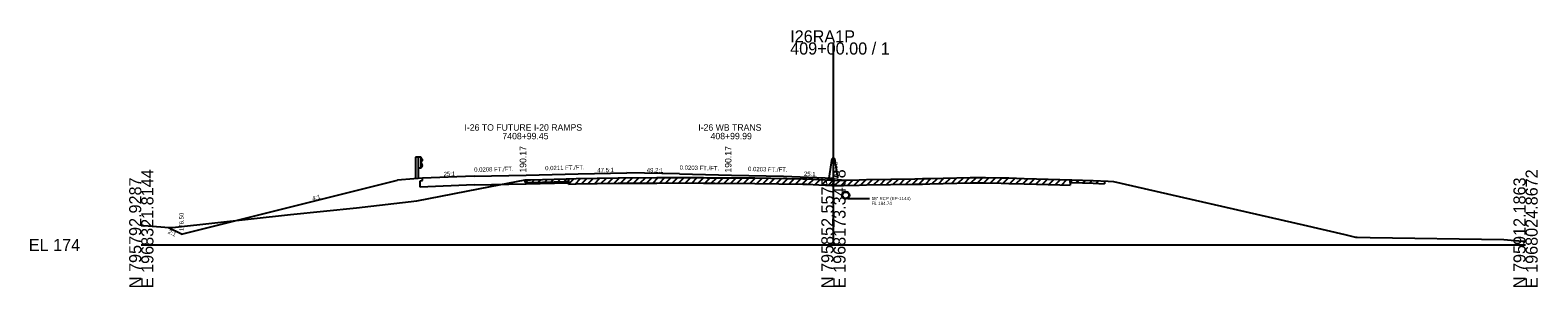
# Model space of a CAD drawing. Extents: x -44 to 4323, y -10 to 9601.
# Drawn here: x -25.7 to 322.8, y 5990.3 to 6049.7 of the extents above; entities that cross this region are included whole.
import ezdxf

# ---------------------------------------------------------------- set-up
doc = ezdxf.new("R2010")
doc.units = 0
for name, color, linetype in [('1', 7, 'Continuous'), ('DateStamp', 7, 'Continuous'), ('NotForConst', 7, 'Continuous'), ('QCQA', 7, 'Continuous'), ('RD_SHT_Bndy', 7, 'Continuous'), ('RD_SHT_Iplotshp', 7, 'Continuous'), ('RD_SHT_TX', 7, 'Continuous'), ('RD_XS_Base', 7, 'Continuous'), ('RD_XS_ExGround', 7, 'Continuous'), ('RD_XS_Misc_Line', 7, 'Continuous'), ('RD_XS_Pave', 7, 'Continuous'), ('RD_XS_PaveShd', 7, 'Continuous'), ('RD_XS_Pipe', 7, 'Continuous'), ('RD_XS_TX_Elev_PR', 7, 'Continuous'), ('RD_XS_TX_ShdSlope', 7, 'Continuous'), ('RD_XS_TX_Slope', 7, 'Continuous'), ('seal', 7, 'Continuous'), ('TR SN EXTRUDED PANEL SIGNS - GROUND MOUNTED', 7, 'Continuous')]:
    doc.layers.add(name, color=color, linetype=linetype)

msp = doc.modelspace()

# ---------------------------------------------------------------- linework, layer by layer
at = {"layer": 'DateStamp'}
msp.add_lwpolyline([(0, 6004.5), (0.57, 6004.47), (6.43, 6004), (7.94, 6004.11), (34.51, 6007.01), (49.78, 6008.61), (63.66, 6010.17), (80.69, 6013.52), (88.75, 6015.06), (89.96, 6015.09), (98.2, 6015.31), (100.53, 6015.35), (110.25, 6015.5), (119.14, 6015.56), (121.94, 6015.59), (129.97, 6015.56), (130.77, 6015.55), (132.56, 6015.54), (141.86, 6015.49), (152.91, 6015.31), (153.94, 6015.29), (156.59, 6015.15), (159.65, 6014.98), (160, 6014.98), (162.31, 6014.99), (165.96, 6015.08), (167.66, 6015.12), (178.84, 6015.3), (180.57, 6015.33), (182.29, 6015.36), (191.59, 6015.58), (192.15, 6015.58), (193.43, 6015.61), (195.13, 6015.6), (198.74, 6015.52), (200.51, 6015.49), (204.13, 6015.38), (206.92, 6015.3), (212.33, 6015.16), (215.08, 6015.07), (220.03, 6014.91), (223.53, 6014.76), (224.74, 6014.71), (268.61, 6004.62), (278.22, 6002.42), (280.71, 6001.82), (281.07, 6001.82), (284.08, 6001.72), (315.01, 6001.29), (319.29, 6000.87), (320, 6000.91)], dxfattribs=at)
at = {"layer": 'NotForConst'}
for p, q in [((88.75, 6014.43), (89.4, 6015.07)), ((90.25, 6014.47), (90.9, 6015.11)), ((91.76, 6014.51), (92.4, 6015.15)), ((93.26, 6014.55), (93.9, 6015.19)), ((94.76, 6014.59), (95.4, 6015.23)), ((96.26, 6014.63), (96.9, 6015.27)), ((97.76, 6014.67), (98.4, 6015.31)), ((98.76, 6014.07), (100.03, 6015.34)), ((100.26, 6014.09), (101.53, 6015.36)), ((101.76, 6014.12), (103.03, 6015.39)), ((103.26, 6014.14), (104.53, 6015.41)), ((104.76, 6014.16), (106.03, 6015.43)), ((106.26, 6014.19), (107.53, 6015.46)), ((107.76, 6014.21), (109.03, 6015.48)), ((109.26, 6014.24), (110.53, 6015.5)), ((110.76, 6014.26), (112.02, 6015.51)), ((112.26, 6014.27), (113.52, 6015.52)), ((113.76, 6014.28), (115.02, 6015.53)), ((115.26, 6014.29), (116.52, 6015.54)), ((116.76, 6014.3), (118.02, 6015.55)), ((118.26, 6014.31), (119.52, 6015.57)), ((119.76, 6014.32), (121.02, 6015.58)), ((121.26, 6014.33), (122.51, 6015.59)), ((122.76, 6014.34), (124.01, 6015.58)), ((124.26, 6014.33), (125.51, 6015.57)), ((125.76, 6014.32), (127.01, 6015.57)), ((127.26, 6014.32), (128.51, 6015.56)), ((128.76, 6014.31), (130.01, 6015.56)), ((130.26, 6014.31), (131.51, 6015.55)), ((131.76, 6014.3), (133.01, 6015.54)), ((133.26, 6014.29), (134.51, 6015.53)), ((134.76, 6014.28), (136.01, 6015.53)), ((136.26, 6014.27), (137.51, 6015.52)), ((137.76, 6014.27), (139.01, 6015.51)), ((139.26, 6014.26), (140.51, 6015.5)), ((140.76, 6014.25), (142.01, 6015.49)), ((142.26, 6014.24), (143.49, 6015.47)), ((143.76, 6014.21), (144.99, 6015.44)), ((145.26, 6014.19), (146.49, 6015.42)), ((146.76, 6014.16), (147.99, 6015.39)), ((148.26, 6014.14), (149.49, 6015.37)), ((149.76, 6014.11), (150.99, 6015.34)), ((151.27, 6014.09), (152.49, 6015.32)), ((152.77, 6014.06), (153.99, 6015.29)), ((154.27, 6014.02), (155.45, 6015.21)), ((155.77, 6013.94), (156.95, 6015.13)), ((157.27, 6013.86), (158.45, 6015.04)), ((158.77, 6013.78), (159.97, 6014.98)), ((160.27, 6013.73), (161.52, 6014.99)), ((161.77, 6013.74), (163.04, 6015.01)), ((163.27, 6013.76), (164.55, 6015.04)), ((164.77, 6013.8), (166.05, 6015.08)), ((166.27, 6013.83), (167.55, 6015.12)), ((167.77, 6013.87), (169.04, 6015.14)), ((169.27, 6013.9), (170.54, 6015.17)), ((170.77, 6013.92), (172.04, 6015.19)), ((172.27, 6013.95), (173.54, 6015.22)), ((173.77, 6013.97), (175.04, 6015.24)), ((175.27, 6013.99), (176.54, 6015.26)), ((176.77, 6014.02), (178.04, 6015.29)), ((178.27, 6014.04), (179.54, 6015.31)), ((179.77, 6014.07), (181.04, 6015.34)), ((181.27, 6014.09), (182.55, 6015.37)), ((182.77, 6014.12), (184.05, 6015.4)), ((184.27, 6014.16), (185.55, 6015.44)), ((185.77, 6014.19), (187.05, 6015.47)), ((187.27, 6014.23), (188.55, 6015.51)), ((188.77, 6014.26), (190.05, 6015.54)), ((190.27, 6014.3), (191.55, 6015.57)), ((191.77, 6014.33), (193.05, 6015.6)), ((193.27, 6014.36), (194.52, 6015.6)), ((194.77, 6014.35), (196, 6015.58)), ((196.27, 6014.32), (197.5, 6015.55)), ((197.77, 6014.29), (199, 6015.52)), ((199.27, 6014.26), (200.5, 6015.49)), ((200.77, 6014.23), (201.99, 6015.44)), ((202.27, 6014.18), (203.49, 6015.39)), ((203.77, 6014.14), (204.99, 6015.35)), ((205.27, 6014.09), (206.49, 6015.31)), ((206.77, 6014.05), (207.99, 6015.27)), ((208.28, 6014.01), (209.49, 6015.23)), ((209.78, 6013.97), (210.99, 6015.19)), ((211.28, 6013.93), (212.49, 6015.15)), ((212.78, 6013.89), (213.99, 6015.1)), ((214.71, 6014.45), (215.32, 6015.06)), ((216.21, 6014.41), (216.82, 6015.01)), ((217.71, 6014.36), (218.32, 6014.96)), ((219.22, 6014.31), (219.82, 6014.92)), ((220.72, 6014.25), (221.31, 6014.85))]:
    msp.add_line(p, q, dxfattribs=at)
at = {"layer": 'QCQA'}
for p, q in [((98.76, 6015.32), (100.53, 6015.35)), ((98.76, 6015.32), (98.76, 6014.34)), ((100.53, 6015.35), (110.25, 6015.5)), ((110.25, 6015.5), (119.14, 6015.56)), ((119.14, 6015.56), (121.94, 6015.59)), ((121.94, 6015.59), (129.97, 6015.56)), ((129.97, 6015.56), (130.77, 6015.55)), ((130.77, 6015.55), (132.56, 6015.54)), ((132.56, 6015.54), (141.86, 6015.49)), ((141.86, 6015.49), (152.91, 6015.31)), ((152.91, 6015.31), (153.94, 6015.29)), ((153.94, 6015.29), (156.59, 6015.15)), ((156.59, 6015.15), (159.65, 6014.98)), ((159.65, 6014.98), (160, 6014.98))]:
    msp.add_line(p, q, dxfattribs=at)
at = {"layer": 'RD_SHT_Bndy'}
for p, q in [((160, 6000), (160, 6046.83)), ((0, 6000), (160, 6000)), ((160, 6000), (320, 6000))]:
    msp.add_line(p, q, dxfattribs=at)
at = {"layer": 'RD_SHT_Iplotshp'}
for p, q in [((88.75, 6014.43), (88.75, 6015.06)), ((88.75, 6014.43), (89.96, 6014.46)), ((89.96, 6014.46), (98.2, 6014.68)), ((98.2, 6014.68), (98.76, 6014.69)), ((98.76, 6014.07), (98.76, 6015.32)), ((98.76, 6015.32), (98.76, 6014.69)), ((98.76, 6014.07), (100.53, 6014.1)), ((100.53, 6014.1), (110.25, 6014.25)), ((110.25, 6014.25), (119.14, 6014.31)), ((119.14, 6014.31), (121.94, 6014.34)), ((121.94, 6014.34), (129.97, 6014.31)), ((129.97, 6014.31), (130.77, 6014.3)), ((130.77, 6014.3), (132.56, 6014.29)), ((132.56, 6014.29), (141.86, 6014.24)), ((141.86, 6014.24), (152.91, 6014.06)), ((152.91, 6014.06), (153.94, 6014.04)), ((153.94, 6014.04), (156.59, 6013.9)), ((156.59, 6013.9), (159.65, 6013.73)), ((159.65, 6013.73), (160, 6013.73)), ((160, 6013.73), (162.31, 6013.74)), ((162.31, 6013.74), (165.96, 6013.83)), ((165.96, 6013.83), (167.66, 6013.87)), ((167.66, 6013.87), (178.84, 6014.05)), ((178.84, 6014.05), (180.57, 6014.08)), ((180.57, 6014.08), (182.29, 6014.11)), ((182.29, 6014.11), (191.59, 6014.33)), ((191.59, 6014.33), (192.15, 6014.33)), ((192.15, 6014.33), (193.43, 6014.36)), ((193.43, 6014.36), (195.13, 6014.35)), ((195.13, 6014.35), (198.74, 6014.27)), ((198.74, 6014.27), (200.51, 6014.24)), ((200.51, 6014.24), (204.13, 6014.13)), ((204.13, 6014.13), (206.92, 6014.05)), ((206.92, 6014.05), (212.33, 6013.91)), ((212.33, 6013.91), (214.71, 6013.83)), ((214.71, 6015.08), (214.71, 6013.83)), ((214.71, 6014.45), (214.71, 6015.08)), ((214.71, 6014.45), (215.08, 6014.44)), ((215.08, 6014.44), (220.03, 6014.28)), ((220.03, 6014.28), (222.7, 6014.17)), ((222.7, 6014.79), (222.7, 6014.17))]:
    msp.add_line(p, q, dxfattribs=at)
at = {"layer": 'RD_XS_Base'}
for p, q in [((64.03, 6020.31), (63.37, 6020.31)), ((63.37, 6020.31), (63.37, 6015.25)), ((64.7, 6020.31), (64.03, 6020.31)), ((64.03, 6020.31), (64.03, 6015.36)), ((64.7, 6017.74), (64.7, 6020.31)), ((64.7, 6020.15), (64.97, 6019.71)), ((64.97, 6019.6), (64.7, 6019.16)), ((64.97, 6019.71), (64.97, 6019.6)), ((64.7, 6017.74), (64.03, 6017.74)), ((64.97, 6018.45), (64.7, 6018.89)), ((64.7, 6017.9), (64.97, 6018.34)), ((64.97, 6018.34), (64.97, 6018.45))]:
    msp.add_line(p, q, dxfattribs=at)
at = {"layer": 'RD_XS_Misc_Line'}
for p, q in [((64.47, 6014.86), (64.97, 6014.88)), ((64.47, 6013.38), (64.47, 6014.86)), ((76.98, 6013.88), (64.47, 6013.38)), ((64.97, 6014.88), (64.97, 6015.44)), ((76.98, 6013.88), (88.99, 6014.13)), ((88.99, 6014.13), (98.76, 6014.34))]:
    msp.add_line(p, q, dxfattribs=at)
at = {"layer": 'RD_XS_Pave'}
for p, q in [((9.3, 6002.5), (59.22, 6014.98)), ((62.97, 6015.28), (59.22, 6014.98)), ((9.3, 6002.5), (6.31, 6003.99))]:
    msp.add_line(p, q, dxfattribs=at)
at = {"layer": 'RD_XS_PaveShd'}
msp.add_line((64.97, 6015.44), (62.97, 6015.28), dxfattribs=at)
at = {"layer": 'RD_XS_Pipe'}
msp.add_line((163.34, 6010.74), (168.34, 6010.74), dxfattribs=at)
for radius in [0.85, 0.75]:
    msp.add_circle((162.84, 6011.49), radius, dxfattribs=at)
at = {"layer": 'RD_XS_TX_Elev_PR'}
for p, q in [((76.98, 6015.92), (64.97, 6015.44)), ((101.01, 6016.42), (112.25, 6016.66)), ((124.43, 6016.41), (112.25, 6016.66)), ((148.43, 6015.92), (160, 6015.46)), ((160, 6015.46), (160, 6014.98))]:
    msp.add_line(p, q, dxfattribs=at)
at = {"layer": 'RD_XS_TX_ShdSlope'}
for p, q in [((159, 6015.48), (159.67, 6019.96)), ((160, 6019.96), (159.67, 6019.96)), ((160, 6019.96), (160.33, 6019.96)), ((161, 6015.48), (160.33, 6019.96))]:
    msp.add_line(p, q, dxfattribs=at)
at = {"layer": 'RD_XS_TX_Slope'}
for p, q in [((76.98, 6015.92), (88.99, 6016.17)), ((88.99, 6016.17), (101.01, 6016.42)), ((124.43, 6016.41), (136.43, 6016.17)), ((136.43, 6016.17), (148.43, 6015.92))]:
    msp.add_line(p, q, dxfattribs=at)

# ---------------------------------------------------------------- texts
at = {"layer": '1'}
for s, p in [('I-26 TO FUTURE I-20 RAMPS', (74.71, 6026.42)), ('I-26 WB TRANS', (128.76, 6026.42)), ('7408+99.45', (83.48, 6024.42)), ('408+99.99', (131.6, 6024.42))]:
    msp.add_text(s, height=1.5, dxfattribs=at).set_placement(p)
at = {"layer": 'RD_SHT_Bndy'}
for s, p in [('I26RA1P', (150, 6046.83)), ('409+00.00 / 1', (150, 6044.03)), ('EL 174', (-26, 5998.6))]:
    msp.add_text(s, height=2.8, dxfattribs=at).set_placement(p)
for s, p in [('E 1968321.8144', (2.8, 5990)), ('E 1968173.3408', (162.8, 5990)), ('E 1968024.8672', (322.8, 5990)), ('N 795792.9287', (0, 5990)), ('N 795852.5575', (160, 5990)), ('N 795912.1863', (320, 5990))]:
    msp.add_text(s, height=2.8, rotation=90, dxfattribs=at).set_placement(p)
at = {"layer": 'RD_SHT_TX'}
msp.add_text('188.98', height=1, rotation=90, dxfattribs=at).set_placement((161, 6014.98))
at = {"layer": 'RD_XS_ExGround'}
for s, rotation, p in [('25:1', 2.2883, (69.91, 6015.89)), ('47.5:1', 1.206, (105.43, 6016.77)), ('49.2:1', 358.8347, (116.85, 6016.82)), ('25:1', 357.7096, (153.17, 6015.98))]:
    msp.add_text(s, height=1, rotation=rotation, dxfattribs=at).set_placement(p)
at = {"layer": 'RD_XS_Pipe'}
for s, p in [('18" RCP (EP-1144)', (168.84, 6010.36)), ('FL 184.74', (168.84, 6009.24))]:
    msp.add_text(s, height=0.75, dxfattribs=at).set_placement(p)
at = {"layer": 'seal'}
for p in [(88.99, 6016.17), (136.43, 6016.17)]:
    msp.add_text(' 190.17', height=1.5, rotation=90, dxfattribs=at).set_placement(p)
at = {"layer": 'TR SN EXTRUDED PANEL SIGNS - GROUND MOUNTED'}
for s, rotation, p in [('0.0208 FT./FT.', 1.1941, (76.96, 6016.92)), ('0.0211 FT./FT.', 1.206, (93.37, 6017.26)), ('0.0203 FT./FT.', 358.8347, (124.45, 6017.41)), ('0.0203 FT./FT.', 358.8347, (140.26, 6017.09)), ('4:1', 14.0362, (39.66, 6010.24)), ('176.50', 90, (9.8, 6003.22)), ('2:1', 333.4349, (6.06, 6002.74))]:
    msp.add_text(s, height=1, rotation=rotation, dxfattribs=at).set_placement(p)

doc.saveas('drawing.dxf')
